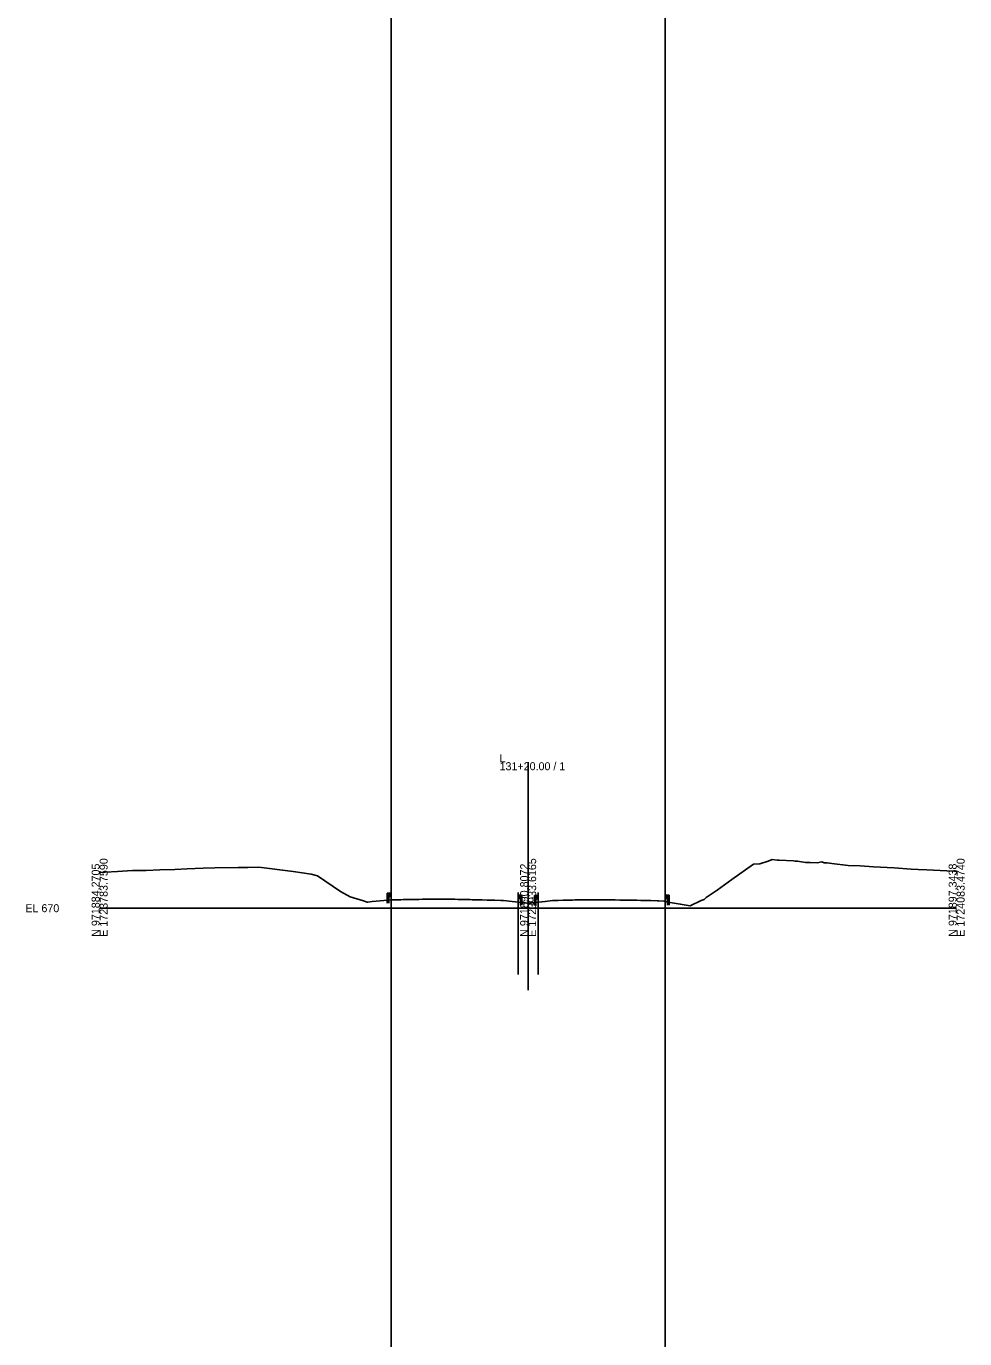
# Model space of a CAD drawing. Extents: x -26 to 303, y -29 to 15026.
# Drawn here: x -25.7 to 302.8, y 1349.3 to 1808.7 of the extents above; entities that cross this region are included whole.
import ezdxf

# ---------------------------------------------------------------- set-up
doc = ezdxf.new("R2010")
doc.units = 0
for name, color, linetype in [('Exist Cross Section Cell', 7, 'Continuous'), ('Exist XS Center Line Elevation Label', 7, 'Continuous'), ('Exist XS Ground Line', 7, 'Continuous'), ('Scratch_Level_0', 7, 'Continuous'), ('Typical Guardrail CELL', 7, 'Continuous')]:
    doc.layers.add(name, color=color, linetype=linetype)

msp = doc.modelspace()

# ---------------------------------------------------------------- linework, layer by layer
at = {"layer": 'Exist Cross Section Cell'}
for p, q in [((150, 1500), (150, 1551.09)), ((0, 1500), (150, 1500)), ((150, 1500), (300, 1500))]:
    msp.add_line(p, q, dxfattribs=at)
at = {"layer": 'Exist XS Ground Line'}
msp.add_lwpolyline([(0, 1512.53), (1.9, 1512.63), (6.26, 1512.89), (11.49, 1513.14), (16.27, 1513.24), (21.09, 1513.41), (26.28, 1513.54), (30.68, 1513.75), (36.29, 1514), (40.27, 1514.12), (48.47, 1514.27), (51.88, 1514.27), (55.74, 1514.34), (67.73, 1512.84), (74.04, 1511.91), (76.32, 1511.34), (84.27, 1505.83), (87.73, 1503.93), (92.42, 1502.56), (93.67, 1502.14), (93.92, 1502.14), (95.4, 1502.29), (102.29, 1502.89), (103.05, 1502.9), (103.67, 1502.92), (105.43, 1502.98), (106.23, 1503), (107.94, 1503.05), (109.53, 1503.07), (110.44, 1503.08), (111.14, 1503.09), (111.74, 1503.1), (112.97, 1503.11), (114.36, 1503.11), (115.45, 1503.12), (116.66, 1503.12), (117.95, 1503.14), (119.27, 1503.13), (120.45, 1503.14), (121.92, 1503.14), (123.09, 1503.15), (124.28, 1503.12), (125.44, 1503.09), (127.09, 1503.06), (127.93, 1503.04), (129.73, 1503), (130.44, 1502.98), (131.08, 1502.97), (132.94, 1502.92), (133.88, 1502.89), (135.71, 1502.84), (137.45, 1502.8), (137.97, 1502.79), (138.3, 1502.78), (140.49, 1502.72), (140.85, 1502.72), (141.38, 1502.71), (144.41, 1502.38), (150.2, 1501.79), (155.95, 1502.4), (158.49, 1502.71), (160.06, 1502.74), (160.49, 1502.75), (162.23, 1502.8), (162.97, 1502.82), (163.68, 1502.84), (164.54, 1502.86), (165.01, 1502.87), (165.5, 1502.87), (166.38, 1502.88), (168, 1502.89), (169.47, 1502.91), (170.5, 1502.92), (171.91, 1502.93), (173.01, 1502.94), (174.21, 1502.95), (175.52, 1502.96), (176.83, 1502.95), (177.31, 1502.95), (178.01, 1502.94), (179.43, 1502.92), (180.5, 1502.9), (182.07, 1502.87), (182.99, 1502.85), (184.65, 1502.82), (185.49, 1502.81), (187.3, 1502.78), (187.99, 1502.76), (189.49, 1502.74), (190.52, 1502.7), (192.53, 1502.65), (193, 1502.65), (195.18, 1502.58), (195.79, 1502.56), (197.5, 1502.5), (198.21, 1502.29), (198.93, 1502.11), (199.68, 1501.97), (203.27, 1501.45), (206.7, 1500.87), (210.52, 1502.64), (211.58, 1503.08), (212.3, 1503.7), (216.21, 1506.34), (221.25, 1510.08), (228.87, 1515.45), (231.1, 1515.52), (233.98, 1516.48), (235.45, 1517.03), (237.17, 1516.86), (237.87, 1516.87), (242.86, 1516.54), (243.49, 1516.44), (244.26, 1516.42), (247.1, 1516.02), (248.71, 1515.96), (251.23, 1515.93), (252.77, 1516.21), (253.6, 1515.88), (254.69, 1515.89), (256.28, 1515.7), (262.02, 1514.93), (266.17, 1514.84), (270.84, 1514.48), (278.16, 1514.16), (284.09, 1513.64), (286.51, 1513.56), (289.62, 1513.47), (296.52, 1513.08), (299.21, 1513.01), (300, 1512.95)], dxfattribs=at)
at = {"layer": 'Scratch_Level_0'}
for p, q in [((102, 15009.56), (102, -28.7)), ((198, 15009.56), (198, -28.7)), ((146.46, 1505.5), (146.46, 1476.8)), ((153.54, 1505.5), (153.54, 1476.8)), ((150, 1500), (150, 1471.3))]:
    msp.add_line(p, q, dxfattribs=at)
at = {"layer": 'Typical Guardrail CELL'}
for p, q in [((101.18, 1505.23), (100.68, 1505.23)), ((100.68, 1505.23), (100.68, 1502.75)), ((101.18, 1502.75), (100.68, 1502.75)), ((100.68, 1502.75), (100.68, 1501.74)), ((101.18, 1505.23), (101.18, 1502.75)), ((101.18, 1505.23), (101.68, 1505.23)), ((101.18, 1504.07), (101.68, 1504.07)), ((101.18, 1502.75), (101.18, 1501.74)), ((101.68, 1505.23), (101.68, 1504.07)), ((101.68, 1505.23), (101.97, 1505.03)), ((101.68, 1504.7), (101.97, 1504.9)), ((101.68, 1504.65), (101.68, 1504.7)), ((101.68, 1504.65), (101.68, 1504.61)), ((101.68, 1504.61), (101.97, 1504.4)), ((101.68, 1504.07), (101.97, 1504.28)), ((146.78, 1504.52), (146.49, 1504.32)), ((146.78, 1503.99), (146.49, 1504.19)), ((146.78, 1503.9), (146.49, 1503.69)), ((146.78, 1503.36), (146.49, 1503.57)), ((147.28, 1504.52), (146.78, 1504.52)), ((146.78, 1504.52), (146.78, 1503.36)), ((146.78, 1503.94), (146.78, 1503.99)), ((146.78, 1503.94), (146.78, 1503.9)), ((147.28, 1503.36), (146.78, 1503.36)), ((147.28, 1504.52), (147.28, 1502.04)), ((147.28, 1504.52), (147.78, 1504.52)), ((147.78, 1504.52), (147.78, 1502.04)), ((152.72, 1504.49), (152.22, 1504.49)), ((152.22, 1504.49), (152.22, 1502)), ((152.72, 1504.49), (152.72, 1502)), ((152.72, 1504.49), (153.22, 1504.49)), ((152.72, 1503.33), (153.22, 1503.33)), ((153.22, 1504.49), (153.22, 1503.33)), ((153.22, 1504.49), (153.51, 1504.29)), ((153.22, 1503.96), (153.51, 1504.16)), ((153.22, 1503.91), (153.22, 1503.96)), ((153.22, 1503.91), (153.22, 1503.86)), ((153.22, 1503.86), (153.51, 1503.66)), ((153.22, 1503.33), (153.51, 1503.53)), ((198.32, 1504.52), (198.03, 1504.32)), ((198.32, 1503.99), (198.03, 1504.19)), ((198.32, 1503.9), (198.03, 1503.7)), ((198.32, 1503.37), (198.03, 1503.57)), ((198.82, 1504.52), (198.32, 1504.52)), ((198.32, 1504.52), (198.32, 1503.37)), ((198.32, 1503.94), (198.32, 1503.99)), ((198.32, 1503.94), (198.32, 1503.9)), ((198.82, 1503.37), (198.32, 1503.37)), ((198.82, 1504.52), (198.82, 1502.04)), ((198.82, 1504.52), (199.32, 1504.52)), ((199.32, 1504.52), (199.32, 1502.04)), ((147.28, 1502.04), (147.78, 1502.04)), ((147.28, 1502.04), (147.28, 1501.03)), ((147.78, 1502.04), (147.78, 1501.03)), ((152.72, 1502), (152.22, 1502)), ((152.22, 1502), (152.22, 1501)), ((152.72, 1502), (152.72, 1501)), ((198.82, 1502.04), (199.32, 1502.04)), ((198.82, 1502.04), (198.82, 1501.03)), ((199.32, 1502.04), (199.32, 1501.03))]:
    msp.add_line(p, q, dxfattribs=at)
for centre, start, end in [((101.92, 1504.97), 304.9888, 54.997), ((101.92, 1504.34), 304.9634, 54.9941), ((146.54, 1504.26), 125.003, 235.0112), ((146.54, 1503.63), 125.0059, 235.0366), ((153.46, 1504.22), 304.9888, 54.997), ((153.46, 1503.6), 304.9634, 54.9941), ((198.08, 1504.26), 125.003, 235.0112), ((198.08, 1503.63), 125.0059, 235.0366)]:
    msp.add_arc(centre, 0.0776, start, end, dxfattribs=at)

# ---------------------------------------------------------------- texts
at = {"layer": 'Exist Cross Section Cell'}
for s, p in [('L', (140, 1551.09)), ('131+20.00 / 1', (140, 1548.29)), ('EL 670', (-26, 1498.6))]:
    msp.add_text(s, height=2.8, dxfattribs=at).set_placement(p)
for s, p in [('E 1723783.7590', (2.8, 1490)), ('E 1723933.6165', (152.8, 1490)), ('E 1724083.4740', (302.8, 1490)), ('N 971884.2705', (0, 1490)), ('N 971890.8072', (150, 1490)), ('N 971897.3438', (300, 1490))]:
    msp.add_text(s, height=2.8, rotation=90, dxfattribs=at).set_placement(p)
at = {"layer": 'Exist XS Center Line Elevation Label'}
msp.add_text('671.81', height=0.18, dxfattribs=at).set_placement((149.67, 1501.32))

doc.saveas('drawing.dxf')
